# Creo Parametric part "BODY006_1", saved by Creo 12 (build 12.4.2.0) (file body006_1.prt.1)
Units: Custom; MM, KILOGRAM, SECS

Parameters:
  PTC_WM_ITERATION = "0"
  PTC_WM_VERSION = "-.0"
  PTC_WM_LIFECYCLE_STATE = "In Work"
  PTC_WM_LIFECYCLE = "MO_CADDocument"
  PTC_WM_CREATED_BY = "Maximilian Roepper (Z0017RMS: MO)"
  PTC_WM_CREATED_ON = "18-Sep-26 11:36:42 AM"
  PTC_WM_MODIFIED_BY = "Maximilian Roepper (Z0017RMS: MO)"
  PTC_WM_MODIFIED_ON = "18-Sep-26 11:36:46 AM"
  PDMLINKNUMBER = "PDM000071455312"
  PTC_WM_NAME = "body006_1.prt"
  PTC_WM_NUMBER = "PDM000071455312"

Other parameters: WEIGHT, WEIGHT_FACTOR, WEIGHT_ADD, _MASS_TEMP, _DIFF_TEMP, MC_ERRORS, SUPPLIER

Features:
  1. coordinate system
  2. datum plane "PRT_YZ"
  3. datum plane "PRT_XY"
  4. datum plane "PRT_XZ"
  5. coordinate system
  6. datum axis
  7. datum axis
  8. datum axis
  9. coordinate system
  10. imported feature

Other named items: PRT, SIEMENS_MO, DRW_VIEW_ORG, PRT_X, PRT_Y, PRT_Z, CS0, ROUGH_GROB

Layers: 00_STD_CSYS-KSYS, 01_STD_PLANES-EBENEN, 02_STD_AXES-ACHSEN, 03_STD_CSYS-KSYS, 24_IMPORT_FEAT-IMPORT_KE

Surfaces: 6 plane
